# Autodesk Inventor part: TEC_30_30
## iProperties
Created: 2006-10
Part Number: TEC_30_30
Document SubType Name: Modeling
Designer: Lab User
Author: Lab User
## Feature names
1. Extrusion1
2. Extrusion2
